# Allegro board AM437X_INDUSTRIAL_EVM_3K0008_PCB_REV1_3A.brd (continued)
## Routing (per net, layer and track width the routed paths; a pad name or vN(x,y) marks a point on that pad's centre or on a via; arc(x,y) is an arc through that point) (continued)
N18075606: length 13.7
  TOP w0.13: U11.T23 82.75,73.96 82.75,77.39 84.25,78.89 84.25,80.23 84.05,80.43 84.05,81.76 84.71,82.42 R74.1
N18139095: length 1.9
  BOTTOM w0.13: U32.7 R300.1
N18167698: length 5.7
  TOP w0.13: C99.2 37.34,25.91 37.59,25.65 38.23,25.65 38.86,26.29 38.86,27.66 39.49,28.29 U23.3
N18181630: length 13.2
  TOP w0.13: R73.1 83.19,85.72 83.19,82.99 82.33,82.13 82.33,81.54 81.46,80.67 81.46,75.79 80.83,75.16 80.83,74.61 U11.P24
N18182281: length 127.2
  TOP w0.13: U23.26 39.49,37.85 v1(38.99,38.35)
  L4_SIG2 w0.13: v1(105.54,87.43) 105.54,87.61 101.51,91.64 100.24,91.64 95.57,96.31 95.57,100.9 v1(96.9,102.23) ; v1(38.99,38.35) 41.09,38.35 41.4,38.66 41.81,38.66 44.82,41.67 44.82,44.58 44.38,45.03 44.38,51.84 46.04,53.5 46.04,54.17 44.77,55.44 44.77,58.66 48.21,62.1 50.73,62.1 54.1,65.48 58.02,65.48 60.42,67.88 60.42,68.76 61.54,69.88 61.54,72.01 62.54,73.01 63.02,73.01 65.52,75.5 65.52,75.5 65.97,75.96 65.97,78.91 67.02,79.95 67.02,82.34 69.33,84.64 69.58,84.64 69.92,84.98 69.92,87.01 76.35,93.45 78.05,93.45 79.07,94.46 v1(81.13,94.46)
  BOTTOM w0.13: v1(81.13,94.46) 82.06,95.39 85.69,95.39 91.9,101.6 96.27,101.6 v1(96.9,102.23) ; R363.2 v1(105.54,87.43)
N18365828: length 4.4
  TOP w0.13: Q2.G 126.28,115.75 Q1.D 125.34,116.95 R2.1
N18365970: length 12.9
  TOP w0.13: v2(125.6,112.52) 125.73,112.65 129.06,112.65 129.18,112.53 129.65,112.53 129.99,112.87 129.99,115.5 R3.1 128.52,115.43 Q2.D
  BOTTOM w0.13: v2(125.6,112.52) 126.31,113.23 U28.3
N18405849: length 39
  TOP w0.13: R68.2 v2(109.98,87.5) ; U11.AC16 86.69,69.39 86.69,69.39 86.65,69.43 v1(86.65,69.45)
  L3_SIG1 w0.13: v1(86.65,69.45) 87.1,69.45 89.15,71.5 94.08,71.5 95.12,72.54 98.7,72.54 101.42,75.26 102.57,75.26 103.48,76.17 v2(104.04,76.17)
  L4_SIG2 w0.13: v2(104.04,76.17) 104.52,76.66 104.52,81.91 106.88,84.27 110.7,84.27 111.21,84.78 111.21,86.27 v2(109.98,87.5)
N18405956: length 45.7
  TOP w0.13: R58.2 v2(109.98,89.79) ; v1(85.68,67.98) U11.AA15
  L3_SIG1 w0.13: v2(105.54,81.15) 105.92,80.77 105.92,80.21 104.85,79.14 104.85,73.99 101.39,70.52 99.26,70.52 97.66,68.92 89.55,68.92 89.03,68.4 87.16,68.4 87.16,68.4 86.11,68.4 v1(85.68,67.98)
  L4_SIG2 w0.13: v2(105.54,81.15) 106.79,82.41 110.68,82.41 111.83,83.55 111.83,86.55 111.5,86.88 111.5,88.65 110.36,89.79 v2(109.98,89.79)
N21620210: length 15.7
  TOP w0.13: v1(69.72,107.19) C3.1 ; U4.3 v1(72.64,97.54)
  L3_SIG1 w0.13: v1(72.64,97.54) 71.13,99.05 71.13,105.02 70.72,105.43 70.72,106.7 70.23,107.19 v1(69.72,107.19)
  BOTTOM w0.13: R295.2 v1(69.72,107.19)
N21620213: length 16.1
  TOP w0.13: v1(71.5,107.19) 72.26,107.95 C4.1 ; U4.5 v1(73.94,97.41)
  L3_SIG1 w0.13: v1(73.94,97.41) 72.39,98.96 72.39,104.43 72.01,104.81 72.01,106.68 v1(71.5,107.19)
  BOTTOM w0.13: R294.2 72.26,107.95 v1(71.5,107.19)
N21620216: length 15.5
  TOP w0.13: U4.7 v1(75.24,97.41) ; v1(74.8,107.19) C5.1
  L3_SIG1 w0.13: v1(75.24,97.41) 73.66,98.99 73.66,104.14 74.42,104.9 74.42,106.81 v1(74.8,107.19)
  BOTTOM w0.13: R293.2 v1(74.8,107.19)
N21620219: length 16.8
  TOP w0.13: U4.9 76.54,97.88 v1(75.44,96.77) ; v1(77.34,107.31) C6.1
  L3_SIG1 w0.13: v1(77.34,107.31) 76.2,106.17 76.2,97.54 v1(75.44,96.77)
  BOTTOM w0.13: R292.2 v1(77.34,107.31)
N21620222: length 15.3
  TOP w0.13: v1(79.88,107.19) C7.1 ; U4.11 v1(77.84,97.41)
  L3_SIG1 w0.13: v1(79.88,107.19) 78.74,106.05 78.74,98.31 v1(77.84,97.41)
  BOTTOM w0.13: R291.2 v1(79.88,107.19)
N21620225: length 10.5
  TOP w0.13: v1(82.42,107.19) C8.1 ; U4.18 77.84,106.16 v1(78.87,107.19)
  L4_SIG2 w0.13: v1(82.42,107.19) 81.66,107.95 79.63,107.95 v1(78.87,107.19)
  BOTTOM w0.13: R290.2 v1(82.42,107.19)
N21620228: length 14.6
  TOP w0.13: v1(78.54,108.05) 78.54,107.62 76.54,105.62 U4.20 ; v1(84.96,107.19) C9.1
  L4_SIG2 w0.13: v1(84.96,107.19) 83.89,108.26 78.74,108.26 v1(78.54,108.05)
  BOTTOM w0.13: R289.2 v1(84.96,107.19)
N21620231: length 21.6
  TOP w0.13: v1(76.3,108.31) 76.3,106.78 75.24,105.72 U4.22 ; v1(88.14,106.81) 88.14,108.65 C10.1
  L4_SIG2 w0.13: v1(76.3,108.31) 76.71,108.71 86.23,108.71 v1(88.14,106.81)
  BOTTOM w0.13: R288.2 87.5,107.44 v1(88.14,106.81)

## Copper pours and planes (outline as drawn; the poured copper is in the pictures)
AGND on TOP (solid shape): 127.95,110.04 127.95,106.23 127.25,105.54 125.15,105.54 125.1,105.57 125.11,105.62 125.16,105.67 125.16,107.25 125.92,108.01 125.92,108.23 125.92,109.79 126.3,110.17 127.82,110.17
AGNDFRAME_PRUETH0 on L5_PWR: 8.76,102.62 11.3,102.62 11.68,102.23 11.68,81.79 10.92,81.03 9.14,81.03 8.38,81.79 8.38,102.23
AGNDFRAME_PRUETH1 on L5_PWR: 8.51,58.04 8.51,78.11 8.89,78.49 11.43,78.49 11.68,78.23 11.68,58.04 11.18,57.53 9.02,57.53
DGND on TOP (solid shape): 30.48,50.42 30.48,48.89 30.23,48.64 28.07,48.64 27.81,48.89 27.81,50.42 28.07,50.67 30.23,50.67
DGND on TOP (solid shape): 46.99,58.67 46.99,55.63 46.74,55.37 45.21,55.37 44.96,55.63 44.96,58.67 45.21,58.93 46.74,58.93
DGND on TOP (solid shape): 52.07,71.88 52.07,70.1 51.56,69.6 49.66,69.6 49.15,70.1 49.15,72.14 49.52,72.5 51.45,72.5
DGND on TOP (solid shape): 52.2,78.74 52.2,76.2 51.94,75.95 49.78,75.95 49.28,76.45 49.28,78.74 49.78,79.25 51.69,79.25
DGND on TOP (solid shape): 63.25,115.82 63.25,111.63 62.99,111.38 61.47,111.38 61.21,111.63 61.21,115.82 61.47,116.08 62.99,116.08
DGND on TOP (solid shape): 110.62,38.23 110.62,35.18 110.36,34.92 108.84,34.92 108.58,35.18 108.58,38.23 108.84,38.48 110.36,38.48
DGND on TOP (solid shape): 112.9,75.56 112.9,72.52 112.65,72.26 111.31,72.26 111,72.58 111,75.63 111.19,75.82 112.65,75.82
DGND on TOP (solid shape): 52.07,65.91 52.07,63.88 51.43,63.25 49.69,63.25 49.15,63.79 49.15,65.15 49.41,65.42 50.05,65.42 50.68,66.04 51.94,66.04
DGND on TOP (solid shape): 127.76,41.78 127.76,40.13 127.38,39.75 123.6,39.75 121.92,39.75 121.54,40.13 121.54,42.04 122.17,42.67 126.87,42.67
DGND on TOP (solid shape): 48.39,34.54 48.39,31.56 48.2,31.19 48.39,30.82 48.39,28.19 48.26,28.07 46.66,28.07 46.46,28.27 46.46,29.87 41.28,29.87 41.28,30.1 40.26,30.1 40.26,29.87 37.46,29.87 37.46,28.58 36.58,28.58 36.58,34.04 36.83,34.29 37.34,34.29 37.59,34.04 37.59,33.53 47.37,33.53 47.37,34.67 48.26,34.67
DGND on BOTTOM (solid shape): 36.83,48.26 36.83,45.08 36.45,44.7 33.78,44.7 33.4,45.09 33.4,48.13 33.66,48.39 36.7,48.39
DGND on BOTTOM (solid shape): 44.96,45.59 44.96,42.04 44.58,41.66 42.42,41.66 42.16,41.91 42.16,45.59 42.42,45.85 44.7,45.85
DGND on BOTTOM (solid shape): 52.07,74.04 52.07,70.1 51.56,69.6 49.66,69.6 49.18,70.07 49.18,72.42 50.93,74.17 51.94,74.17
DGND on BOTTOM (solid shape): 52.07,67.82 52.07,64.01 51.31,63.25 49.66,63.25 49.18,63.72 49.18,66.32 50.8,67.95 51.94,67.95
DGND on BOTTOM (solid shape): 52.2,80.65 52.2,76.71 51.43,75.95 49.78,75.95 49.28,76.45 49.28,78.99 51.05,80.77 52.07,80.77
DGND on BOTTOM (solid shape): 107.7,106.43 107.7,104.96 107.44,104.71 105.73,104.71 105.41,105.03 105.41,106.43 105.79,106.81 107.31,106.81
DGND on BOTTOM (solid shape): 115.7,89.28 115.7,85.6 115.44,85.34 113.16,85.34 112.9,85.6 112.9,89.15 113.28,89.53 115.44,89.53
DGND on BOTTOM (solid shape): 17.4,59.94 17.4,57.66 14.83,57.66 14.57,57.4 14.35,57.4 13.97,57.78 13.97,59.82 14.48,60.32 17.02,60.32
DGND on BOTTOM (solid shape): 113.41,51.94 113.41,48.26 113.16,48.01 110.87,48.01 110.62,48.26 110.62,50.7 110.62,50.7 110.62,51.82 111,52.2 113.16,52.2
DGND on BOTTOM (solid shape): 124.46,86.11 124.46,82.93 124.08,82.55 122.11,82.55 122.1,82.55 121.97,82.58 121.84,82.55 121.83,82.55 121.41,82.55 121.03,82.93 121.03,86.11 121.41,86.49 124.08,86.49
DGND on BOTTOM (solid shape): 43.69,36.2 43.69,33.78 43.94,33.53 47.62,33.53 47.88,33.27 47.88,30.1 47.62,29.84 38.1,29.84 37.72,30.23 37.72,33.27 37.97,33.53 41.27,33.53 41.53,33.78 41.53,36.2 41.71,36.38 41.74,36.36 42.04,36.34 42.26,36.55 42.27,36.58 43.31,36.58
DGND on BOTTOM (solid shape): 121.16,48.39 121.44,47.86 122.13,47.79 122.17,47.71 122.17,45.59 121.79,45.21 119.54,45.21 119.29,45.44 118.95,45.43 118.92,45.42 118.75,45.59 118.75,48.77 119.13,49.15 121.16,49.15
DGND on BOTTOM (solid shape): 114.3,71.25 114.68,70.87 114.68,69.22 114.43,68.96 113.97,68.96 113.9,69 113.87,69.07 113.41,69.55 112.95,69.07 112.93,69 112.85,68.96 112.62,68.96 112.62,68.96 112.14,68.96 111.76,69.34 111.76,70.74 112.27,71.25
DGND on BOTTOM (solid shape): 52.07,58.42 52.07,54.48 51.68,54.09 51.58,54.07 51.51,54.15 51.02,54.56 50.6,54.08 50.57,54.01 50.5,53.98 50.32,53.98 50.24,54.01 50.22,54.08 49.92,54.53 49.4,54.39 49.33,54.35 49.25,54.38 49.18,54.45 49.18,56.8 50.93,58.55 51.94,58.55
DGND on BOTTOM (solid shape): outline of 97 points within 123.57,52.32 131.57,59.94
DGND on TOP: 127.38,77.09 124.21,77.09 123.83,77.47 123.83,79.12 124.84,80.14 124.84,81.03 125.48,81.66 127.38,81.66 127.76,81.28 127.76,77.47
DGND on TOP: 78.11,64.01 78.61,64.01 79.17,63.45 85.08,63.45 85.73,64.1 85.73,64.38 84.58,65.53 84.58,67.31 83.57,68.33 83.57,69.85 84.45,70.74 84.45,71.38 83.95,71.88 83.06,71.88 82.42,71.25 76.83,71.25 76.37,70.78 76.37,70.57 76.83,70.1 76.83,68.45 77.47,67.82 77.47,64.64
DGND on TOP: 33.27,62.48 35.31,62.48 35.81,61.98 35.81,60.32 34.92,59.44 34.54,59.44 33.15,60.83 31.62,60.83 30.48,61.98 30.48,64.26 30.73,64.52 31.24,64.52
DGND on TOP: 41.66,63.37 46.23,63.37 49.28,60.32 58.29,60.32 59.31,61.34 67.31,61.34 67.56,61.09 67.56,60.45 66.8,59.69 59.56,59.69 58.67,58.8 49.15,58.8 47.21,60.74 42.02,60.74 41.15,61.62 41.15,62.86
DGND on TOP: 64.01,116.08 65.41,116.08 66.42,115.06 66.42,112.9 66.17,112.65 64.9,112.65 63.75,113.79 63.75,115.82
DGND on TOP: 61.85,31.5 62.48,31.5 62.86,31.88 63.12,31.88 63.37,31.62 64.52,31.62 64.9,31.24 64.9,29.59 64.39,29.08 62.86,29.08 61.59,30.35 61.59,31.24
DGND on TOP: 33.4,73.28 33.78,72.9 33.78,71.63 33.27,71.12 28.96,71.12 28.7,71.37 28.7,72.64 29.34,73.28
DGND on TOP: 81.58,91.03 79.04,91.03 78.28,91.8 78.28,93.78 78.59,94.08 81.33,94.08 81.84,93.57 81.84,91.29
DGND on TOP: 38.1,84.96 39.62,84.96 40,84.58 40,80.14 46.1,74.04 46.1,72.14 48.89,69.34 57.78,69.34 58.17,68.96 58.17,68.33 57.02,67.18 48.51,67.18 44.32,71.37 44.32,73.91 40.26,77.98 39.5,77.98 37.59,79.88 37.59,84.45
DGND on TOP: 31.37,52.83 30.99,52.45 30.35,52.45 30.1,52.7 30.1,53.72 29.34,54.48 27.18,54.48 27.05,54.61 27.05,55.88 27.18,56.01 30.48,56.01 31.37,55.12
DGND on TOP: 47.37,111.63 47.88,112.14 48.77,112.14 49.15,111.76 49.15,110.87 50.29,109.73 50.29,107.82 49.15,106.68 49.15,106.05 48.77,105.66 47.88,105.66 47.37,106.17
DGND on TOP: 33.66,44.32 36.83,44.32 36.96,44.45 36.96,45.72 36.83,45.85 33.66,45.85 33.4,45.59 33.4,44.58
DGND on TOP: 87.76,96.65 93.6,96.65 94.23,96.01 94.23,93.73 93.85,93.34 87.63,93.34 87.12,93.85 87.12,96.01
DGND on TOP: 87.38,84.71 89.53,84.71 90.04,85.22 90.04,86.23 88.77,87.5 87.63,87.5 87.12,87 87.12,84.96
DGND on TOP: 18.29,100.71 22.48,100.71 23.11,100.08 34.67,100.08 35.18,99.57 35.18,97.66 34.67,97.16 22.48,97.16 20.7,98.93 19.81,98.93 18.92,98.04 17.78,98.04 17.14,98.68 17.14,99.57
DGND on TOP: 23.62,22.99 26.67,22.99 28.07,21.59 28.07,16 27.56,15.49 23.49,15.49 23.11,15.88 23.11,22.48
DGND on TOP: 92.58,16.89 92.08,16.89 91.31,17.65 89.53,17.65 88.9,18.29 88.9,19.43 89.15,19.69 91.57,19.69 91.82,19.43 91.82,18.16 92.58,17.4
DGND on TOP: 33.4,49.4 31.62,49.4 31.37,49.66 31.37,52.2 32.13,52.96 32.13,53.59 32.51,53.98 33.78,53.98 33.91,53.85 33.91,49.91
DGND on TOP: 37.34,76.58 41.02,76.58 41.4,76.2 41.4,74.8 41.02,74.42 37.34,74.42 36.96,74.8 36.96,76.2
DGND on TOP: 117.22,27.05 118.87,27.05 120.52,28.7 120.52,32.77 120.02,33.27 113.03,33.27 111.63,31.88 111.63,27.43 112.52,26.54 116.71,26.54
DGND on BOTTOM: 103,94.87 102.71,94.58 102.46,94.58 102.14,94.9 103,95.76 103.63,95.76 105.16,97.28 105.16,98.3 105.41,98.55 106.43,98.55 106.68,98.3 106.68,95.12 106.43,94.87
DGND on BOTTOM: 81.84,91.29 81.58,91.03 79.02,91.03 78.23,91.82 78.23,93.73 78.59,94.08 81.33,94.08 81.84,93.57
DGND on BOTTOM: 33.4,99.69 35.18,99.69 40.13,94.74 40.13,94.49 35.69,94.49 35.31,94.87 35.31,96.01 33.91,97.41 33.02,97.41 32.38,98.04 32.38,98.68
DGND on BOTTOM: 26.54,92.84 30.56,92.84 30.99,92.41 30.99,91.19 30.73,90.93 29.72,90.93 28.58,89.79 26.54,89.79 26.16,90.17 26.16,92.46
DGND on BOTTOM: 45.09,18.41 45.09,16.89 44.7,16.51 41.27,16.51 41.02,16.76 41.02,18.54 41.27,18.8 44.7,18.8
DGND on BOTTOM: 119.89,29.84 120.52,30.48 120.52,33.15 119.13,34.54 113.03,34.54 111.63,33.15 111.63,30.73 112.52,29.84
DGND on BOTTOM: 40.51,89.66 41.15,89.66 41.4,89.41 41.4,87 40.13,85.72 40.13,84.07 39.37,83.31 37.08,83.31 36.83,83.57 36.83,85.98
DGND on BOTTOM: 12.83,22.86 15.11,22.86 15.49,22.48 15.49,21.21 14.61,20.32 14.61,16.89 14.1,16.38 12.95,16.38 12.45,16.89 12.45,22.48
DGND on BOTTOM: 87.76,87.5 89.28,87.5 90.04,86.74 90.04,85.72 89.28,84.96 87.76,84.96 87.38,85.34 87.38,87.12
DGND on BOTTOM: 76.45,69.72 76.45,70.87 77.47,71.88 81.15,71.88 81.79,71.25 83.44,71.25 83.82,71.63 85.34,71.63 85.85,71.12 87.25,71.12 87.38,71.25 87.38,71.63 87.63,71.88 90.04,71.88 90.3,71.63 90.3,69.85 89.28,68.83 87.63,68.83 87.12,68.33 87.12,63.88 86.74,63.5 82.93,63.5 82.68,63.75 81.53,63.75 81.28,63.5 79.38,63.5 79.25,63.37 77.6,63.37 77.47,63.5 76.58,63.5 76.07,64.01 76.07,69.34 ; 1 cut-out
DGND on BOTTOM: 65.15,115.06 65.41,115.32 66.8,115.32 66.93,115.44 66.93,116.59 66.8,116.71 61.59,116.71 61.09,116.2 61.09,111.89 61.47,111.51 63.12,111.51 63.5,111.89 64.9,111.89 65.15,112.14
DGND on BOTTOM: 71.5,99.57 74.42,99.57 75.95,98.04 77.22,98.04 77.47,98.3 77.47,99.44 77.85,99.82 81.66,99.82 82.04,100.2 82.04,101.47 81.79,101.73 80.26,101.73 80.01,101.98 80.01,105.66 79.5,106.17 77.22,106.17 76.71,105.66 76.71,103.89 76.2,103.38 74.17,103.38 73.02,102.23 71.5,102.23 71.12,101.85 71.12,99.95
DGND on BOTTOM: 129.16,114.68 130.56,114.68 130.81,114.94 131.19,114.94 131.44,114.68 131.44,113.03 131.19,112.78 129.16,112.78 128.91,113.03 128.91,114.43
DGND on BOTTOM: 56.52,70.61 57.78,70.61 58.67,69.72 62.23,69.72 63.12,70.61 66.04,70.61 68.83,67.82 72.52,67.82 72.64,67.69 72.64,67.31 72.39,67.06 56.52,67.06 55.75,67.82 55.75,69.85
DGND on BOTTOM: 99.82,98.68 99.31,99.19 97.28,99.19 96.77,98.68 96.77,96.65 97.28,96.14 99.44,96.14 99.82,96.52
DGND on BOTTOM: 7.37,11.05 9.91,11.05 10.29,10.67 10.29,8.51 9.53,7.75 7.75,7.75 6.99,8.51 6.99,10.67
DGND on BOTTOM: 33.73,57.68 31.62,59.79 31.62,61.47 32.26,62.1 35.94,62.1 35.94,60.96 38.23,60.96 39.12,60.07 39.12,59.31 37.49,57.68
DGND on BOTTOM: 65.91,105.16 66.93,105.16 67.18,104.9 67.18,103.12 65.53,101.47 63.12,101.47 62.61,101.98 62.61,104.01 63.12,104.52 63.88,104.52 64.14,104.77 64.14,106.68 64.39,106.93 65.15,106.93 65.66,106.43 65.66,105.41
DGND on BOTTOM: 101.22,88.27 100.84,87.88 98.81,87.88 98.42,88.27 98.42,90.8 100.71,93.09 101.24,93.09 101.37,92.96 101.37,92.1 101.22,91.95
DGND on BOTTOM: 114.17,16 119.89,16 120.52,15.37 120.52,11.05 119.51,10.03 114.3,10.03 113.28,11.05 113.28,15.11
DGND on BOTTOM: 23.49,22.86 26.8,22.86 27.43,22.23 27.43,19.94 28.07,19.3 28.07,16.38 26.8,15.11 23.75,15.11 23.11,15.75 23.11,22.48
DGND on BOTTOM: 56.64,96.01 67.95,96.01 68.2,96.27 68.2,97.92 67.82,98.3 56.77,98.3 56.39,97.92 56.39,96.27
DGND on BOTTOM: 98.3,45.21 102.49,45.21 103.12,44.58 103.12,42.16 102.49,41.53 98.42,41.53 97.79,42.16 97.79,44.7
DGND on L2_GND: 2.53,118.73 137.17,118.73 138.71,117.2 138.71,2.18 137.8,1.27 54.51,1.27 53.91,1.87 42.23,1.87 41.63,1.27 2.54,1.27 1.3,2.51 1.3,117.5
DGND on L3_SIG1: 16.76,102.87 20.07,102.87 22.48,100.46 22.48,93.34 20.07,90.93 20.07,87.63 20.7,87 29.34,87 30.61,85.72 30.61,84.58 29.59,83.57 20.07,83.57 19.3,82.8 19.3,76.71 25.91,70.1 25.91,65.79 27.81,63.88 29.21,63.88 29.97,63.12 29.97,61.98 29.34,61.34 26.8,61.34 21.34,66.8 21.34,69.98 14.99,76.33 14.99,83.82 14.22,84.58 14.22,100.33
DGND on L3_SIG1: 29.59,72.14 38.96,72.14 41.91,69.19 53.37,69.19 58.12,64.43 60.92,64.43 61.85,63.5 63.63,63.5 63.88,63.25 63.88,62.23 63.12,61.47 58.04,61.47 53.75,65.76 48.51,65.76 48.23,66.04 41.99,66.04 37.8,70.23 29.84,70.23 29.08,70.99 29.08,71.63 ; 1 cut-out
DGND on L3_SIG1: 47.24,90.55 50.19,90.55 53.11,87.63 58.67,87.63 61.34,84.96 61.34,78.23 61.77,77.8 61.77,73.33 56.98,68.54 55.88,69.65 55.88,71.25 59.56,74.93 59.56,76.45 59.84,76.73 59.84,78.84 59.82,78.87 59.82,84.84 58.93,85.72 54.74,85.72 54.23,85.22 50.55,85.22 46.86,88.9 46.86,90.17
DGND on L4_SIG2: 63.3,75.36 63.3,76.23 61.39,78.13 61.39,85.65 61.93,86.18 61.93,87.27 61.61,87.59 60.68,87.59 59.82,86.73 59.82,77.8 59.79,77.77 59.79,75.62 59.41,75.23 57.07,75.23 55.44,73.6 55.44,70.24 56.13,69.55 57.2,69.55 57.53,69.88 57.53,70.1 57.78,70.36 57.84,70.36 59.99,72.52 60.45,72.52
DGND on L4_SIG2: 16.51,103 22.23,103 22.86,102.36 22.86,71.75 25.02,69.6 25.02,67.44 24.51,66.93 22.35,66.93 19.3,69.98 19.3,72.26 14.86,76.71 14.86,101.35
DGND on L4_SIG2: 50.18,85.61 47.19,88.6 47.19,89.94 47.57,90.32 56.62,90.32 57.4,89.53 57.4,86.23 56.78,85.61
DGND on L5_PWR: 94.23,55.12 94.23,54.46 94.84,53.85 95.5,53.85 96.81,52.54 96.81,49.62 102.36,44.07 102.69,44.07 103.12,43.64 103.12,21.84 100.2,18.92 95.15,18.92 93.88,20.19 73.66,20.19 64.77,29.08 64.77,30.35 62.36,32.77 62.36,51.43 64.77,53.85 64.77,54.99 66.29,56.52 66.29,57.53 67.44,58.67 67.82,58.67 70.74,61.59 74.68,61.59 75.31,62.23 77.85,62.23 79.12,63.5 83.44,63.5 84.45,64.52 85.47,64.52 85.72,64.26 85.72,63.63
GND_ETH1 on BOTTOM: 26.67,108.33 45.85,108.33 47.5,109.98 47.5,112.39 47.24,112.65 27.43,112.65 26.16,113.92 25.53,113.92 25.27,113.66 25.27,109.73
GND_OSC0 on TOP: 69.72,79.25 69.72,89.79 71.12,91.19 74.8,91.19 75.56,90.42 75.56,85.98 74.55,84.96 74.55,75.44 73.91,74.8 72.9,74.8 72.64,75.06 72.64,76.33
GND_OSC0 on L2_GND: 70.61,81.28 70.61,90.17 71.63,91.19 74.8,91.19 75.56,90.42 75.56,85.98 74.9,85.32 74.9,75.79 73.91,74.8 73.3,74.8 73.15,74.96 73.15,78.74
GND_OSC1 on BOTTOM: 102.74,64.26 103.25,63.75 103.25,58.29 102.74,57.78 91.95,57.78 89.92,59.82 88.77,59.82 87.5,61.09 86.87,61.09 86.61,61.34 86.61,62.36 88.52,64.26 ; 1 cut-out
GNDA_ADC on TOP: 120.02,117.86 121.92,115.95 121.92,109.35 121.16,108.58 118.62,108.58 117.73,107.7 115.57,107.7 115.19,107.31 113.92,107.31 112.9,108.33 112.9,115.7 115.06,117.86
GNDA_ADC on TOP: 63.88,31.88 64.77,31.88 65.79,30.86 65.79,28.32 66.8,27.3 66.8,22.1 74.93,13.97 77.34,13.97 78.41,15.04 78.41,17.86 67.18,29.08 67.18,31.88 66.17,32.89 64.01,32.89 63.63,32.51 63.63,32.13
GNDA_ADC on TOP: 112.14,90.3 115.7,90.3 116.33,90.93 116.97,90.93 117.22,90.68 117.22,87.5 116.71,87 112.14,87 111.89,87.25 111.89,90.04
GNDA_ADC on L3_SIG1: 105.84,76.07 107.57,76.07 108.01,75.63 108.01,74.99 108.33,74.68 108.33,73.28 111.89,69.72 111.89,66.93 110.24,65.28 108.84,65.28 105.41,61.85 88.27,61.85 87.38,62.74 87.38,63.25 87.76,63.63 103.25,63.63 104.27,64.64 104.27,66.04 103,67.31 100.84,67.31 100.84,69.77 105.21,74.14 105.21,75.44
GNDA_ADC on L4_SIG2: 93.85,42.42 96.27,42.42 97.16,41.53 97.16,37.08 96.52,36.45 95.5,36.45 93.22,38.73 93.22,41.78
GNDUSBJ on BOTTOM (solid shape): 136.87,60.8 136.87,59.29 137.58,59.29 137.58,59.56 138.66,59.56 138.66,55.12 135.73,55.12 135.23,55.63 135.23,60.93 136.75,60.93
GNDUSBJ on BOTTOM (solid shape): 138.66,70.1 138.66,66.09 137.58,66.09 137.58,66.69 136.87,66.69 136.87,65.06 136.84,65.02 136.69,65.02 136.65,65.06 135.15,65.06 135.1,65.11 135.1,65.6 134.81,65.89 134.81,70.23 135.06,70.48 138.27,70.48
GNDUSBJ on L3_SIG1: 136.4,56.13 135.64,56.9 135.64,58.55 136.53,59.44 136.53,69.85 137.03,70.36 138.3,70.36 138.73,69.93 138.73,56.94 137.92,56.13
V1_5D on TOP: 129.29,100.46 131.06,100.46 131.44,100.08 131.44,98.3 131.06,97.92 129.41,97.92 128.91,98.42 128.91,100.08
V1_5D on TOP: 128.14,89.03 129.79,89.03 130.18,88.65 130.18,88.01 129.79,87.63 128.14,87.63 127.89,87.88 127.89,88.77
V1_5D on BOTTOM: 60.45,40.89 61.34,40 62.74,40 62.99,40.26 62.99,41.15 62.23,41.91 62.23,43.94 58.04,48.13 49.78,48.13 49.15,48.77 45.72,48.77 45.21,48.26 45.21,44.07 48.39,40.89
V1_5D on BOTTOM: 80.39,63.25 81.03,63.25 81.53,62.74 81.53,62.36 80.77,61.59 80.77,58.8 80.52,58.55 80.14,58.55 79.88,58.8 79.88,62.74
V1_5D on L3_SIG1: 128.4,88.9 129.41,88.9 129.79,88.52 129.79,86.23 129.54,85.98 129.16,85.98 127.89,87.25 127.89,88.39
V1_5D on L3_SIG1: 51.56,43.05 54.48,43.05 61.09,36.45 62.36,36.45 62.61,36.7 62.61,44.45 66.42,48.26 67.82,48.26 78.87,59.31 79.63,59.31 81.28,60.96 81.28,62.1 82.04,62.86 83.44,62.86 83.69,63.12 83.69,63.88 83.31,64.26 77.47,64.26 61.21,48.01 51.56,48.01 50.67,47.12 50.67,43.94
V1_5D on L3_SIG1: 96.27,24.13 100.08,24.13 100.84,23.37 100.84,22.1 96.58,17.84 94.17,17.84 92.96,16.64 91.57,16.64 90.8,17.4 90.8,18.67
V1_5D on L4_SIG2: 78.99,64.26 83.19,64.26 83.69,63.75 83.69,62.86 83.06,62.23 78.99,62.23 78.49,62.74 78.49,63.75
V1_5DREG on BOTTOM (solid shape): 45.85,52.07 45.85,51.69 43.31,49.15 42.8,49.15 41.53,47.88 41.53,46.86 39.62,44.96 37.46,44.96 37.21,45.21 37.21,51.31 37.46,51.56 43.56,51.56 44.32,52.32 45.59,52.32
V1_8D on TOP: 94.36,100.97 99.31,100.97 99.69,100.58 99.69,99.19 99.31,98.81 98.17,98.81 97.66,99.31 94.23,99.31 94.11,99.44 94.11,100.71
V1_8D on BOTTOM: 112.27,87.38 109.98,87.38 108.08,85.47 108.08,82.93 108.71,82.3 112.14,82.3 112.65,82.8 112.65,87
V1_8D on L3_SIG1: 104.77,60.32 106.81,60.32 107.44,59.69 107.44,53.72 108.97,52.2 108.97,50.67 108.46,50.16 104.39,50.16 103.63,50.93 103.63,59.18
V1_8D on L4_SIG2: 106.05,86.87 106.05,87.73 98.81,94.97 98.81,104.52 105.92,111.63 106.81,111.63 107.34,111.1 107.34,103.48 106.02,102.16 106.02,92.99 108.58,90.42 108.58,88.27 110.74,86.11 110.74,84.96 110.49,84.71 108.2,84.71
V1_8D on L5_PWR: 108.71,86.11 111,86.11 111.76,85.34 111.76,60.83 108.08,57.15 105.66,57.15 105.47,57.34 105.47,60.01 108.08,62.61 108.08,63.75 104.39,67.44 104.39,76.58 107.95,80.14 107.95,85.34
V1_8D_AM437X on TOP: 81.84,88.62 81.46,88.24 78.64,88.24 78.23,88.65 78.23,90.42 78.59,90.78 81.58,90.78 81.84,90.53
V1_8D_AM437X on TOP: 94.36,98.93 96.14,98.93 96.9,98.17 96.9,97.16 96.39,96.65 95.76,96.65 95.12,97.28 94.36,97.28 94.11,97.54 94.11,98.68
V1_8D_AM437X on BOTTOM: 81.43,90.78 81.84,90.37 81.84,88.62 81.46,88.24 79.3,88.24 78.61,88.93 78.61,90.3 79.1,90.78
V1_8D_AM437X on BOTTOM: 86.74,91.06 89.41,91.06 89.66,91.31 89.66,93.34 89.28,93.73 86.74,93.73 86.23,93.22 86.23,91.57
V1_8D_AM437X on BOTTOM: 103.76,72.14 105.16,72.14 105.28,72.01 105.28,69.22 105.03,68.96 104.01,68.96 102.84,67.79 102.26,67.79 101.88,68.17 101.88,69.11 102.49,69.72 103,69.72 103.63,70.36 103.63,72.01
V1_8D_AM437X on BOTTOM: 69.34,83.57 71.12,83.57 71.63,83.06 71.63,81.66 71.5,81.53 69.85,81.53 69.09,82.3 69.09,83.31
V1_8D_AM437X on L3_SIG1: 73.79,72.77 73.02,72.77 72.2,73.6 72.2,78.42 76.66,82.88 76.66,88.09 83.57,95 91.06,95 95.15,99.09 99.16,99.09 100.33,97.92 100.33,95.81 96.08,91.55 90.82,91.55 89.87,90.6 84.63,90.6 80.77,86.74 80.77,81.65 75.95,76.82 75.95,74.93
V1_8D_AM437X on L5_PWR: 103.63,59.44 96.06,67.01 96.06,79.81 98.42,82.17 98.42,89.79 96.39,91.82 85.98,91.82 82.8,88.65 78.23,88.65 77.47,89.41 75.69,89.41 70.61,84.33 70.61,82.3 69.85,81.53 68.83,81.53 68.07,82.3 68.07,85.09 67.56,85.6 67.56,87.5 68.52,88.46 70.42,88.46 72.33,90.36 73.85,90.36 74.68,91.19 83.06,91.19 86.11,94.23 90.04,94.23 94.36,98.55 96.77,98.55 101.47,93.85 101.47,79.76 100.46,78.74 100.46,74.17 103.76,70.87 103.76,68.2 108.08,63.88 108.08,62.36 105.16,59.44
V1_8DADC on BOTTOM: 127.89,115.19 131.85,115.19 132.21,115.54 132.21,116.59 131.95,116.84 128.27,116.84 127.76,116.33 127.76,115.32
V1_8DREG on BOTTOM (solid shape): outline of 136 points within 112.01,78.87 120.65,87.12
V1_8FTDI on BOTTOM: 111.76,57.78 112.14,57.4 112.14,56.13 111.76,55.75 109.73,55.75 109.35,56.13 109.35,57.4 109.73,57.78
V1_8FTDI on L3_SIG1: 111.38,55.5 111.76,55.12 119.89,55.12 120.4,55.63 120.4,60.32 123.57,63.5 126.62,63.5 127.64,62.48 127.64,55.75 124.08,52.2 109.55,52.2 107.89,53.85 107.89,62.86 108.81,63.78 110.49,63.78 110.49,63.75 111.38,62.86
V2_5MTR on L5_PWR: 51.43,39.37 55.37,39.37 59.56,35.18 59.56,28.58 57.4,26.42 51.18,26.42 49.91,27.69 49.91,37.85
V2_8A on TOP (solid shape): 130.62,112.2 130.62,110.8 130.36,110.55 126.04,110.55 125.54,110.04 125.54,108.39 124.77,107.63 124.77,107.12 124.77,106.61 124.77,105.83 124.62,105.67 124.51,105.65 124.44,105.74 124.44,105.91 124.08,106.27 124.08,106.67 123.76,106.99 123.76,107.5 123.85,107.68 123.89,107.88 123.89,108.65 123.85,108.85 123.76,109.03 123.76,109.79 126.17,112.2 128.87,112.2 128.99,112.09 129.84,112.09 130.28,112.53
V2_8D on TOP: 128.78,110.24 131.19,110.24 131.44,109.98 131.44,109.09 130.94,108.58 128.91,108.58 128.65,108.84 128.65,110.11
V2_8D on TOP: 116.84,92.84 116.84,91.57 116.59,91.31 115.82,91.31 115.57,91.57 115.57,93.85 116.46,94.74 117.86,94.74 118.11,94.49 118.11,93.34 117.86,93.09 117.09,93.09
V2_8D on BOTTOM: 116.2,104.9 117.98,104.9 118.24,105.16 118.24,107.95 117.73,108.46 116.46,108.46 115.95,107.95 115.95,105.16
V2_8D on L4_SIG2: 135.38,96.52 132.59,93.73 117.86,93.73 116.2,95.38 116.2,107.44 121.03,112.27 130.05,112.27 132.33,109.98 132.33,100.84 135.38,97.79
V2_8D_OUT on BOTTOM (solid shape): 117.6,104.27 117.6,102.49 117.35,102.23 110.74,102.23 110.55,102.43 110.56,102.43 110.56,103.95 110.62,104.01 110.87,104.01 110.88,104.01 111.01,103.96 111.15,103.95 114.05,103.95 114.05,104 114.07,104.01 114.17,104.01 114.55,104.39 117.47,104.39
V3_3D on TOP (solid shape): 52.07,56.39 52.07,54.36 51.43,53.72 49.66,53.72 49.15,54.23 49.15,55.4 49.3,55.4 49.3,55.34 49.31,55.28 49.32,55.22 49.35,55.17 49.38,55.12 49.41,55.07 49.46,55.03 49.5,54.99 49.56,54.96 49.61,54.94 49.67,54.92 49.73,54.91 49.79,54.91 49.85,54.92 49.91,54.94 49.96,54.96 50.01,54.99 50.06,55.03 50.1,55.07 50.14,55.12 50.17,55.17 50.19,55.22 50.21,55.28 50.22,55.34 50.22,55.4 50.21,55.46 50.19,55.52 50.17,55.57 50.14,55.63 50.1,55.67 50.06,55.72 50.01,55.75 49.96,55.78 49.91,55.81 49.85,55.82 49.79,55.83 49.73,55.83 49.67,55.82 49.61,55.81 49.56,55.78 49.5,55.75 49.46,55.72 49.41,55.67 49.38,55.63 49.35,55.57 49.32,55.52 49.31,55.46 49.3,55.4 49.15,55.4 49.15,56.26 49.29,56.39 49.31,56.39 49.34,56.39 49.37,56.38 49.42,56.33 49.46,56.29 49.51,56.25 49.57,56.23 49.62,56.2 49.68,56.19 49.74,56.18 49.8,56.19 49.86,56.2 49.92,56.21 49.97,56.24 50.03,56.27 50.07,56.31 50.11,56.35 50.15,56.4 50.18,56.45 50.2,56.52 51.94,56.52
V3_3D on BOTTOM (solid shape): 123.7,66.8 123.7,66.17 121.41,63.88 118.75,63.88 118.49,64.14 118.49,65.15 118.62,65.28 119.86,65.28 119.98,65.41 120.02,65.41 120.33,65.72 120.33,67.24 120.91,67.82 122.68,67.82
V3_3D on BOTTOM (solid shape): 107.82,104.07 108.97,104.07 109.09,103.95 109.09,102.92 109.05,102.83 108.36,102.76 108.08,102.23 108.08,101.86 108.07,101.85 107.57,101.85 107.19,102.23 105.79,102.23 105.41,102.62 105.41,104.01 105.72,104.33 107.57,104.33
V3_3D on TOP: 94.49,10.79 94.49,11.3 94.77,11.58 94.77,13.13 95.71,13.13 96.27,12.57 98.55,12.57 98.81,12.83 98.81,14.48 99.57,15.24 100.2,15.24 100.33,15.11 100.33,10.92 100.08,10.67 94.61,10.67
V3_3D on TOP: 41.91,74.8 41.91,72.01 42.16,71.75 43.69,71.75 43.94,72.01 43.94,73.79 42.67,75.06 42.16,75.06
V3_3D on TOP: 94.87,106.43 92.2,106.43 91.57,105.79 91.57,102.87 91.69,102.74 92.84,102.74 93.09,103 93.09,103.89 93.22,104.01 95.25,104.01 95.38,104.14 95.38,105.92
V3_3D on TOP: 67.18,106.43 67.95,106.43 68.2,106.68 70.1,106.68 70.48,106.3 70.48,102.36 69.98,101.85 67.82,101.85 66.93,102.74 66.93,106.17
V3_3D on BOTTOM: 134.85,90.55 135.76,90.55 136.02,90.3 136.02,88.01 135.64,87.63 135.51,87.63 134.75,88.39 134.75,90.45
V3_3D on BOTTOM: 26.16,99.31 28.7,99.31 28.96,99.06 28.96,97.79 28.58,97.41 26.8,97.41 26.03,98.17 26.03,99.19
V3_3D on BOTTOM: 128.91,73.28 129.16,73.28 129.92,72.52 130.56,72.52 130.94,72.14 130.94,71.37 130.56,70.99 129.41,70.99 128.78,71.63 128.78,73.15
V3_3D on BOTTOM: 67.82,106.93 72.52,106.93 73.53,105.92 73.53,103.76 73.02,103.25 71.63,103.25 69.85,101.47 67.56,101.47 67.18,101.85 67.18,102.62 67.56,103 67.56,106.68
V3_3D on BOTTOM: 132.34,50.67 133.22,50.67 133.35,50.8 133.35,52.83 133.1,53.09 132.72,53.09 132.34,52.71
V3_3D on BOTTOM: 129.79,84.45 130.68,84.45 130.68,86.61 130.43,86.87 130.05,86.87 129.79,86.61
V3_3D on BOTTOM: 103,90.93 102.49,91.44 102.49,92.08 102.62,92.2 103.25,92.2 103.5,91.95 106.17,91.95 106.68,92.46 106.68,93.34 106.43,93.6 104.14,93.6 103.89,93.85 102.74,93.85 102.62,93.98 102.62,94.11 103.12,94.61 106.68,94.61 107.06,95 107.06,98.55 106.68,98.93 103.12,98.93 102.74,98.55 102.74,97.92 102.62,97.79 102.11,97.79 101.85,97.54 101.85,96.77 101.32,96.24 101.32,94.2 101.22,94.2 101.22,93.85 101.09,93.85 100.2,94.74 100.2,98.81 99.82,99.19 99.82,101.35 100.2,101.73 107.06,101.73 108.71,100.08 108.71,91.95 107.7,90.93
V3_3D on L3_SIG1: 119.13,46.86 128.27,46.86 129.54,45.59 129.54,43.05 128.4,41.91 119.13,41.91 118.11,42.93 118.11,45.85
V3_3D on L4_SIG2: 41.76,5.59 49.78,5.59 51.82,3.56 57.02,3.56 60.58,7.11 60.58,18.8 59.69,19.69 42.04,19.69 40.31,17.96 40.31,7.04
V3_3D on L4_SIG2: 136.4,76.45 127.25,85.6 119.38,85.6 117.6,87.38 117.6,91.44 119.13,92.96 134.62,92.96 135.89,94.23 135.89,98.3 132.97,101.22 132.97,108.2 133.6,108.84 135.38,108.84 136.53,107.7 136.53,102.62 138.68,100.46 138.68,77.22 137.92,76.45
V3_3D on L5_PWR: 3.16,118.1 46.12,118.1 47.37,116.84 47.37,107.7 49.02,106.05 82.55,106.05 84.43,107.92 89.41,107.92 91.29,106.05 117.47,106.05 120.02,103.5 120.02,73.02 125.09,67.95 125.09,65.41 120.02,60.32 120.02,41.66 111.76,33.4 111.76,15.88 109.22,13.34 100.71,13.34 99.95,12.57 99.06,12.57 98.3,13.34 33.81,13.34 28.45,18.69 28.45,28.19 31.5,31.24 31.5,36.58 37.46,42.55 37.46,58.67 36.07,60.07 33.66,60.07 26.03,52.45 26.03,49.91 24.38,48.26 3.17,48.26 1.91,49.53 1.91,116.84
V3_3D_AM437X on TOP (solid shape): 54.99,56.26 54.99,54.1 54.36,53.47 52.96,53.47 52.45,53.98 52.45,56.26 52.7,56.52 54.74,56.52
V3_3D_AM437X on TOP (solid shape): 55.24,65.48 55.24,63.88 54.61,63.25 52.83,63.25 52.45,63.63 52.45,64.26 52.45,64.77 52.45,66.04 52.46,66.05 54.67,66.05
V3_3D_AM437X on TOP (solid shape): 54.99,71.75 54.99,69.72 54.61,69.34 52.83,69.34 52.45,69.72 52.45,70.23 52.45,70.74 52.45,71.25 52.45,71.76 52.7,72.01 54.74,72.01
V3_3D_AM437X on TOP (solid shape): 55.12,77.82 55.12,76.5 55.1,76.47 55.07,76.45 54.81,76.33 54.71,76.05 54.69,75.98 54.61,75.95 52.96,75.95 52.58,76.33 52.58,76.71 52.58,77.22 52.58,77.72 52.58,78.61 52.83,78.87 54.07,78.87
V3_3D_AM437X on BOTTOM (solid shape): 54.99,56.9 54.99,54.1 54.36,53.47 52.96,53.47 52.45,53.98 52.45,58.29 52.7,58.55 53.34,58.55
V3_3D_AM437X on BOTTOM (solid shape): 55.24,66.29 55.24,63.88 54.61,63.25 52.83,63.25 52.45,63.63 52.45,66.17 52.45,66.68 52.45,67.69 52.7,67.95 53.59,67.95
V3_3D_AM437X on BOTTOM (solid shape): 54.99,72.52 54.99,69.98 54.36,69.34 52.96,69.34 52.45,69.85 52.45,70.23 52.45,70.74 52.45,71.25 52.45,71.76 52.45,73.91 52.7,74.17 53.34,74.17
V3_3D_AM437X on BOTTOM (solid shape): 55.12,79.12 55.12,76.58 55.06,76.52 55.04,76.52 54.78,76.39 54.65,76.13 54.65,76.11 54.48,75.95 53.34,75.95 52.58,76.71 52.58,78.99 52.58,79.5 52.58,80.01 52.58,80.52 52.83,80.77 53.47,80.77
V3_3D_AM437X on L3_SIG1: 83.57,68.83 82.68,69.72 77.85,69.72 77.34,69.22 77.34,65.15 77.72,64.77 77.72,62.99 77.47,62.74 76.83,62.74 75.95,63.63 75.95,70.48 77.72,72.26 79.76,72.26 81.91,74.42 86.61,74.42 86.61,69.98 85.47,68.83
V3_3D_AM437X on L5_PWR: 52.45,54.23 52.45,76.96 53.85,78.36 61.09,78.36 61.47,77.98 61.47,76.71 62.36,75.82 73.66,75.82 75.82,73.66 75.82,69.72 77.22,68.33 77.22,65.41 77.85,64.77 77.85,62.86 77.47,62.48 72.01,62.48 68.3,66.19 61.09,66.19 57.91,63.02 57.91,54.48 56.26,52.83 53.85,52.83
V3_3D_PRUETH0JCK on BOTTOM: 12.7,95.89 18.67,95.89 20.83,93.73 20.83,84.84 19.94,83.95 13.21,83.95 12.07,85.09 12.07,95.25
V3_3D_PRUETH1JCK on BOTTOM: 12.7,70.48 18.67,70.48 19.94,71.75 20.57,71.75 20.83,71.5 20.83,62.74 18.8,60.71 13.72,60.71 12.07,62.36 12.07,69.85
V3_3DREG on BOTTOM (solid shape): outline of 137 points within 53.26,102.74 67.06,111.51
V3_3DREG on L3_SIG1: 14.61,51.94 17.4,51.94 18.03,51.31 18.03,50.7 17.75,50.42 14.35,50.42 14.1,50.67 14.1,51.43
V3_3DREG on L4_SIG2: 61.47,19.43 65.41,19.43 66.29,18.54 66.29,15.37 67.44,14.22 69.22,14.22 69.98,13.46 69.98,9.65 67.03,6.71 62.92,6.71 60.83,8.79 60.83,18.8
V3_3DREG on L4_SIG2: 55.52,107.42 56.52,108.41 57.1,108.41 57.38,108.13 57.38,106.91 56.41,105.94 55.91,105.94 55.52,106.32
V3_3DREG on L4_SIG2: 13.97,51.43 17.4,51.43 17.93,50.9 17.93,50.06 17.4,49.53 13.97,49.53 13.34,50.16 13.34,50.8
V3_3FTDI on BOTTOM (solid shape): outline of 242 points within 110.88,55.5 119.89,68.58
V3_3FTDI on TOP: 121.92,58.17 123.32,56.77 129.16,56.77 132.21,53.72 132.21,52.45 131.44,51.69 127.89,51.69 124.84,54.74 121.92,54.74 121.54,55.12 121.54,55.88 121.28,56.13 113.28,56.13 111.76,54.61 111.76,51.94 114.17,49.53 114.17,45.34 113.79,44.96 108.08,44.96 107.31,45.72 107.31,54.74 110.74,58.17
V3_3FTDI on TOP: 128.65,67.44 127.76,68.33 127.76,69.09 128.65,69.98 133.48,69.98 137.41,73.91 137.41,74.8 137.8,75.18 138.3,75.18 138.68,74.8 138.68,70.1 136.02,67.44
V3_3FTDI on BOTTOM: 127.76,67.82 129.03,67.82 129.29,67.56 129.29,65.66 130.05,64.9 130.05,64.52 129.79,64.26 128.02,64.26 127.51,64.77 127.51,67.56
V3_3FTDI on BOTTOM: 131.19,50.67 132.08,50.67 132.08,52.83 131.83,53.09 131.44,53.09 131.19,52.83
V3_3FTDI on L3_SIG1: 119.45,56.01 112.08,56.01 112.08,65.73 112.9,66.55 112.9,69.09 113.28,69.47 129.79,69.47 130.94,68.33 130.94,65.41 129.54,64.01 123.51,64.01 120.62,61.12 119.45,59.95
V3_3MTR on L3_SIG1: 52.45,23.37 59.05,23.37 60.2,22.23 60.2,21.08 60.83,20.45 61.47,20.45 62.86,21.84 62.86,33.78 58.93,37.72 51.56,37.72 48.26,41.02 41.27,41.02 40.13,39.88 40.13,36.2 40.89,35.43 49.02,35.43 49.91,34.54 58.67,34.54 60.07,33.15 60.07,28.58 57.53,26.03 52.58,26.03 51.69,25.15 51.69,24.13
V5_0D on BOTTOM (solid shape): outline of 122 points within 8.89,52.2 20.57,57.28
V5_0D on TOP: 125.98,117.98 125.98,116.71 126.11,116.59 127.76,116.59 127.89,116.71 127.89,117.98 127.64,118.24 126.24,118.24
V5_0D on BOTTOM: 30.61,20.83 31.62,20.83 31.75,20.95 31.75,23.11 31.24,23.11 30.48,22.35 30.48,20.95
V5_0D on BOTTOM: 110.74,112.39 103.76,105.41 98.42,105.41 97.92,105.92 90.3,105.92 88.65,107.57 88.65,116.33 90.42,118.11 125.98,118.11 126.11,118.24 128.02,118.24 128.27,117.98 128.27,117.35 127.76,116.84 127,116.84 126.75,116.59 126.75,115.32 126.49,115.06 123.32,115.06 120.65,112.39
V5_0D on L4_SIG2: 1.91,11.43 1.91,107.95 12.07,118.11 103.38,118.11 104.27,117.22 104.27,111.38 101.98,109.09 46.99,109.09 44.4,106.5 27.46,106.5 25.53,108.43 16.87,108.43 11.94,103.5 11.94,19.3 14.86,16.38 20.83,16.38 28.7,24.26 32.89,24.26 38.1,19.05 38.1,15.75 36.32,13.97 36.32,8.76 32.77,5.21 8.13,5.21
V5_0VOP on L4_SIG2: 76.81,105.26 80.06,105.26 80.7,104.62 80.7,96.7 76.96,92.96 73.41,92.96 72.64,93.73 72.64,95.38 73.28,96.01 73.66,96.01 76.45,98.81 76.45,104.9
V24_0D on TOP (solid shape): 121.03,41.66 121.03,40 121.67,39.37 123.44,39.37 124.08,38.73 124.08,36.7 123.44,36.07 119.76,36.07 119.13,36.7 119.13,37.18 119.13,39.91 118.78,40.26 116.46,40.26 116.33,40.39 116.33,41.27 116.59,41.53 119.38,41.53 119.63,41.78 120.9,41.78
V24_0D on TOP: 34.42,53.98 34.04,54.36 32.26,54.36 31.75,54.86 31.75,55.37 30.61,56.52 27.18,56.52 25.53,54.86 21.72,54.86 21.34,55.24 21.34,58.55 21.59,58.8 22.48,58.8 22.73,58.55 22.73,56.52 22.99,56.26 24.51,56.26 26.8,58.55 33.02,58.55 33.78,59.31 35.94,59.31 36.45,58.8 36.45,54.1 36.83,53.72 38.99,53.72 39.24,53.47 39.24,52.58 38.99,52.32 36.32,52.32 36.2,52.2 34.54,52.2 34.42,52.32
V24_0D on TOP: 55.24,109.6 55.5,109.35 55.5,108.58 55.24,108.33 52.58,108.33 52.32,108.08 50.93,108.08 50.8,108.2 50.8,109.86 49.53,111.12 49.53,114.81 49.91,115.19 52.32,115.19 52.7,114.81 52.7,110.11 53.21,109.6
V24_0D on TOP: 118.87,77.47 118.62,77.72 118.62,78.61 118.87,78.87 121.54,78.87 121.79,79.12 123.19,79.12 123.32,78.99 123.32,77.34 123.95,76.71 125.73,76.71 126.36,76.07 126.36,74.04 125.73,73.41 122.05,73.41 121.41,74.04 121.41,77.09 121.03,77.47
V24_0D on TOP: 112.52,17.91 120.52,17.91 121.79,19.18 121.79,26.29 121.28,26.8 119.51,26.8 119.25,26.54 117.35,26.54 116.97,26.16 112.27,26.16 111.63,25.53 111.63,18.8
V24_0D on BOTTOM: 112.27,17.91 120.52,17.91 121.79,19.18 121.79,26.8 120.14,28.45 113.54,28.45 111.76,26.67 111.76,18.41
V24_0D on L5_PWR: 50.67,118.62 136,118.62 138.09,116.53 138.09,2.84 136.53,1.27 55.37,1.27 54.48,2.16 41.53,2.16 41.27,1.91 3.17,1.91 1.91,3.17 1.91,46.99 2.79,47.88 24.89,47.88 26.54,49.53 26.54,52.32 33.66,59.44 35.69,59.44 36.83,58.29 36.83,42.67 30.86,36.7 30.86,31.37 27.76,28.27 27.76,18.34 33.27,12.83 108.71,12.83 111.89,16 111.89,32.77 120.14,41.02 120.14,60.58 124.84,65.28 124.84,68.33 120.14,73.02 120.14,104.77 118.11,106.81 91.41,106.81 89.79,108.43 84.68,108.43 83.06,106.81 50.55,106.81 48.89,108.46 48.89,116.84
V24_0MTR on TOP: 14.73,23.75 20.7,23.75 21.34,23.11 21.34,16.89 20.57,16.13 17.14,16.13 14.1,19.18 14.1,23.11
V24_0MTR on BOTTOM: 16.26,16.51 21.46,16.51 22.23,17.27 22.23,22.35 21.72,22.86 16.51,22.86 15.75,22.1 15.75,21.08 15.11,20.45 15.11,17.65
V24_0MTR on BOTTOM: 36.32,36.2 39.75,36.2 40,35.94 40,33.78 39.88,33.66 37.72,33.66 37.21,33.15 37.21,29.84 36.96,29.59 35.56,29.59 35.18,29.97 35.18,35.05
V24_0MTR on L4_SIG2: 46.1,29.46 46.1,26.67 44.7,25.27 28.32,25.27 20.07,17.02 17.14,17.02 16.26,17.91 16.26,23.75 24.38,31.88 43.69,31.88
VDD_CORE on BOTTOM (solid shape): 110.24,50.55 110.24,45.21 109.6,44.58 109.25,44.58 109.22,44.59 109.17,44.61 109.1,44.62 109.04,44.63 108.98,44.62 108.92,44.61 108.86,44.59 108.83,44.58 104.52,44.58 103.63,45.47 103.63,47.53 107.62,47.53 107.62,47.47 107.63,47.41 107.64,47.35 107.67,47.3 107.7,47.24 107.73,47.2 107.77,47.15 107.82,47.12 107.87,47.09 107.93,47.06 107.99,47.05 108.05,47.04 108.11,47.04 108.17,47.05 108.22,47.06 108.28,47.09 108.33,47.12 108.38,47.15 108.42,47.2 108.46,47.24 108.49,47.3 108.51,47.35 108.53,47.41 108.53,47.47 108.53,47.53 108.53,47.59 108.51,47.65 108.49,47.7 108.46,47.75 108.42,47.8 108.38,47.84 108.33,47.88 108.28,47.91 108.22,47.93 108.17,47.95 108.11,47.96 108.05,47.96 107.99,47.95 107.93,47.93 107.87,47.91 107.82,47.88 107.77,47.84 107.73,47.8 107.7,47.75 107.67,47.7 107.64,47.65 107.63,47.59 107.62,47.53 103.63,47.53 103.63,47.62 103.12,48.13 98.42,48.13 97.92,48.64 97.92,50.42 98.68,51.18 109.6,51.18
VDD_CORE on TOP: 56.77,15.88 58.55,15.88 58.93,15.49 58.93,14.35 58.17,13.59 57.28,13.59 56.39,14.48 56.39,15.49
VDD_CORE on BOTTOM: 106.05,65.91 107.57,65.91 108.08,65.41 108.08,64.14 107.57,63.63 105.92,63.63 105.41,64.14 105.41,65.28
VDD_CORE on L3_SIG1: 79.5,67.95 82.17,67.95 83.06,67.06 83.06,65.41 82.3,64.64 78.49,64.64 77.85,65.28 77.85,66.29
VDD_CORE on L5_PWR: 107.95,44.7 102.62,44.7 96.65,50.67 96.65,53.24 95.71,54.18 95.3,54.18 94.41,55.07 94.41,55.83 86.11,64.14 78.99,64.14 77.98,65.15 77.98,66.04 79.12,67.18 79.12,67.69 80.64,69.22 80.64,70.99 81.28,71.63 94.36,71.63 95.5,70.48 95.5,67.18 104.77,57.91 104.77,52.7 106.81,50.67 108.46,50.67 109.98,49.15 109.98,46.74
VDD_COREREG on BOTTOM (solid shape): 118.36,48.64 118.36,42.55 118.11,42.29 112.14,42.29 111.38,41.53 109.98,41.53 109.73,41.78 109.73,42.16 112.14,44.58 112.65,44.58 114.05,45.97 114.05,46.86 114.17,46.99 116.46,46.99 116.84,47.37 116.84,48.64 117.09,48.89 118.11,48.89
VDD_MPU on TOP: 90.8,90.42 96.27,90.42 97.92,88.77 97.92,85.6 97.28,84.96 93.73,84.96 93.22,85.47 93.22,87.12 92.84,87.5 90.93,87.5 90.55,87.88 90.55,90.17
VDD_MPU on TOP: 87.38,84.33 89.03,84.33 89.15,84.2 89.15,82.55 88.77,82.17 87.5,82.17 87.12,82.55 87.12,84.07
VDD_MPU on TOP: 64.45,27.49 65.23,27.49 65.66,27.06 65.66,25.93 65.13,25.4 64.39,25.4 64.01,25.78 64.01,27.05
VDD_MPU on BOTTOM: 94.36,87.88 96.65,87.88 96.9,88.14 97.41,88.14 97.79,87.76 97.79,85.47 97.41,85.09 93.6,85.09 93.22,85.47 93.22,87.76 93.6,88.14 94.11,88.14
VDD_MPU on L3_SIG1: 64.68,27.53 65.82,27.53 66.67,26.67 66.67,25.65 66.04,25.02 65.02,25.02 64.38,25.66 64.38,27.23
VDD_MPU on L3_SIG1: 78.11,69.34 78.99,69.34 79.38,68.96 79.38,68.33 78.74,67.69 77.85,67.69 77.6,67.95 77.6,68.83
VDD_MPU on L5_PWR: 97.79,89.53 97.79,82.42 95.38,80.01 95.38,73.41 94.36,72.39 81.41,72.39 80.01,70.99 80.01,69.85 78.74,68.58 78.74,67.44 78.36,67.06 77.95,67.06 77.57,67.44 77.57,68.48 76.2,69.85 76.2,74.3 93.09,91.19 96.14,91.19
VDD_MPU_OUT on BOTTOM: 98.93,95.5 94.49,95.5 93.85,94.87 93.85,93.47 94.36,92.96 100.46,92.96 100.84,93.34 100.84,93.6
VDD_MPU_SENSE on BOTTOM: 94.11,92.58 97.79,92.58 98.04,92.33 98.04,88.52 97.79,88.27 94.74,88.27 93.85,89.15 93.85,92.33
VDDA_MC_ADC on BOTTOM: 101.22,72.26 103,72.26 103.25,72.01 103.25,70.36 103.12,70.23 102.49,70.23 101.98,69.72 101.35,69.72 100.97,70.1 100.97,72.01
VDDR_VREF on TOP: 83.31,11.94 78.93,16.32 78.93,17.97 75.31,21.59 75.31,23.11 76.07,23.88 78.74,23.88 87.63,14.99 90.42,14.99 92.2,13.21 92.96,13.21 93.09,13.08 93.09,12.07 92.96,11.94
VDDR_VREF on BOTTOM: 84.84,33.15 87.38,33.15 87.63,32.89 87.63,31.75 86.11,30.23 84.2,30.23 83.31,31.12 83.31,31.62
VDDR_VREF on BOTTOM: 67.77,35.05 68.96,35.05 69.34,34.67 69.34,34.16 70.66,32.84 70.66,28.19 69.65,27.18 68.48,27.18 67.06,28.6 67.06,29.54 66.55,30.05 66.55,33.83
VDDR_VREF on BOTTOM: 73.79,27.69 77.34,27.69 78.61,26.42 78.61,23.24 77.85,22.48 76.33,22.48 73.41,25.4 73.41,27.3
VDDR_VREF on L4_SIG2: 94.08,32.26 96.27,32.26 97.1,31.42 97.1,27.03 96.39,26.31 94.23,26.31 93.42,27.13 93.42,31.6
VDDR_VTT on TOP: 92.21,18.13 92.21,20.26 91.5,20.97 84.31,20.97 84.07,21.21 84.07,21.97 84.33,22.23 88.39,22.23 89.92,23.75 96.52,23.75 101.85,29.08 101.85,32.38 102.11,32.64 103.5,32.64 103.89,32.26 103.89,26.02 99.59,21.72 96.39,21.72 96.14,21.97 94.23,21.97 93.77,21.51 93.77,17.85 92.71,17.85 92.42,18.13
VDDR_VTT on BOTTOM: 97.16,20.83 96.01,21.97 94.36,21.97 92.33,19.94 88.9,19.94 86.86,17.9 84.57,17.9 83.82,18.65 83.82,24.18 83.11,24.89 83.11,28.5 83.95,29.34 84.45,29.34 84.84,28.96 84.84,26.42 86.11,25.15 98.68,25.15 100.58,27.05 100.58,30.23 103.25,32.89 103.25,33.4 101.6,35.05 99.19,35.05 98.81,35.43 98.81,35.94 99.19,36.32 103.76,36.32 104.39,35.69 104.39,27.67 103.77,27.05 103.77,21.73 102.87,20.83
VDDS_DDR on TOP: 87.12,27.94 87.76,27.3 90.42,27.3 95.12,32 95.12,33.91 94.61,34.42 94.61,36.07 94.23,36.45 88.77,36.45 87.12,34.8
VDDS_DDR on TOP: 94.74,16.51 95.12,16.89 95.12,17.4 95.76,18.03 95.76,19.56 96.14,19.94 96.14,21.39 95.94,21.59 94.49,21.59 94.23,21.34 94.23,16.51
VDDS_DDR on BOTTOM: 79.88,16 76.07,19.81 71.96,19.81 63.5,28.27 63.5,36.58 63.25,36.83 63.25,42.19 63.63,42.57 64.82,42.57 65.68,41.71 65.68,39.52 66.22,38.99 66.22,29.92 66.67,29.47 66.67,28.45 68.83,26.29 69.6,26.29 70.74,25.15 73.02,25.15 76.07,22.1 78.11,22.1 79.04,23.04 81.13,23.04 82.37,24.28 83.03,24.28 83.44,23.88 83.44,16.51 84.07,15.88 86.74,15.88 90.3,19.43 92.33,19.43 94.49,21.59 95.76,21.59 96.01,21.34 96.01,18.16 95.89,18.03 93.85,18.03 91.19,15.37 88.14,15.37 87.12,14.35 83.95,14.35 82.3,16
VDDS_DDR on L3_SIG1: 78.61,30.73 77.6,30.73 75.06,33.27 75.06,33.78 75.56,34.29 77.72,34.29 78.87,33.15 78.87,30.99
VDDS_DDR on L3_SIG1: 87.88,37.97 87.12,38.73 71.88,38.73 70.48,37.34 70.48,35.69 71.25,34.92 71.25,29.46 70.1,28.32 64.39,28.32 64.01,28.7 64.01,34.54 63.37,35.18 63.37,43.56 64.77,44.96 65.53,44.96 66.42,44.07 66.42,41.91 66.67,41.66 97.66,41.66 97.66,28.7 97.03,28.07 95.89,28.07 95.76,28.19 95.76,32 95.38,32.38 94.23,32.38 92.33,34.29 90.04,34.29 87.88,36.45
VDDS_DDR on L4_SIG2: 69.72,34.42 77.85,34.42 79.38,35.94 79.38,40.26 78.11,41.53 69.6,41.53 69.22,41.15 69.22,34.92
VDDS_DDR on L4_SIG2: 94.11,21.59 94.11,18.67 94.61,18.16 94.61,15.88 96.39,14.1 98.81,14.1 99.06,14.35 99.06,16 98.42,16.64 98.42,17.27 97.28,18.41 97.28,21.34 96.65,21.97 94.49,21.97
(no net) on TOP: 53.21,109.98 55.37,109.98 56.59,111.2 56.59,113.84 56.39,114.05 54.61,114.05 53.09,112.52 53.09,110.11
(no net) on TOP: 43.31,27.18 43.56,27.43 43.69,27.43 44.32,26.8 45.34,26.8 46.61,25.53 46.61,22.35 47.24,21.72 50.93,21.72 51.56,21.08 51.56,17.4 50.8,16.64 47.6,16.64 47.43,16.81 47.43,16.81 43.69,20.55 43.69,26.42 43.31,26.8
(no net) on TOP: 54.99,56.26 54.99,54.1 54.36,53.47 52.96,53.47 52.45,53.98 52.45,56.26 52.7,56.52 54.74,56.52
(no net) on TOP: 42.04,24.89 42.04,27.05 42.29,27.3 42.8,27.3 42.8,27.05 42.93,26.92 42.93,17.14 42.55,16.76 38.23,16.76 37.85,17.14 37.85,20.7
(no net) on TOP: 116.59,40.13 116.33,40.39 116.33,41.27 116.59,41.53 119.38,41.53 119.63,41.78 120.9,41.78 121.03,41.66 121.03,40 121.67,39.37 123.44,39.37 124.08,38.73 124.08,36.7 123.44,36.07 119.76,36.07 119.13,36.7 119.13,39.75 118.75,40.13
(no net) on TOP: 52.2,71.75 52.2,70.23 51.56,69.6 49.66,69.6 49.15,70.1 49.15,72.14 49.53,72.52 51.43,72.52
(no net) on TOP: 58.04,109.98 60.07,109.98 60.32,110.24 60.32,114.81 59.94,115.19 57.4,115.19 56.9,114.68 56.9,111.12
(no net) on TOP: 52.2,65.79 52.2,64.01 51.43,63.25 49.66,63.25 49.15,63.75 49.15,65.15 50.04,66.04 51.94,66.04
(no net) on TOP: 38.61,25.4 40.64,27.43 40.64,29.72 40.89,29.72 40.89,28.07 41.32,27.65 41.32,25.82 36.45,20.95 36.45,19.05 34.16,16.76 30.48,16.76 29.84,17.4 29.84,19.56 35.69,25.4
(no net) on TOP: 120.9,77.22 118.62,77.22 117.53,76.12 117.53,73.36 117.73,73.15 119.51,73.15 121.03,74.68 121.03,77.09
(no net) on TOP: 63.25,111.63 62.99,111.38 61.47,111.38 61.21,111.63 61.21,115.82 61.47,116.08 62.99,116.08 63.25,115.82
(no net) on TOP: 122.17,42.67 126.87,42.67 127.76,41.78 127.76,40.13 127.38,39.75 121.92,39.75 121.54,40.13 121.54,42.04
(no net) on TOP: 36.96,53.98 39.24,53.98 40.34,55.07 40.34,57.84 40.13,58.04 38.35,58.04 36.83,56.52 36.83,54.1
(no net) on TOP: 41.78,53.98 43.81,53.98 44.07,54.23 44.07,58.55 43.56,59.05 41.15,59.05 40.64,58.55 40.64,55.12
(no net) on TOP: 22.99,53.98 22.99,51.94 23.24,51.69 29.21,51.69 29.59,52.07 29.59,53.59 29.21,53.98 24.77,53.98 24.51,54.23 23.24,54.23
(no net) on TOP: 127.95,110.04 127.95,106.23 127.25,105.54 125.09,105.54 125.09,107.19 125.92,108.01 125.92,109.79 126.3,110.17 127.82,110.17
(no net) on TOP: 52.32,78.61 52.32,76.33 51.94,75.95 49.78,75.95 49.28,76.45 49.28,78.74 49.78,79.25 51.69,79.25
(no net) on TOP: 118.62,39.88 116.33,39.88 115.24,38.79 115.24,36.02 115.44,35.81 117.22,35.81 118.75,37.34 118.75,39.75
(no net) on TOP: 116.08,77.22 114.05,77.22 113.79,76.96 113.79,72.64 114.17,72.26 116.84,72.26 117.22,72.64 117.22,76.07
(no net) on TOP: 110.87,75.56 111.12,75.82 112.65,75.82 112.9,75.56 112.9,72.52 112.65,72.26 111.12,72.26 110.87,72.52
(no net) on TOP: 52.2,56.26 52.2,54.48 51.43,53.72 49.66,53.72 49.15,54.23 49.15,56.26 49.4,56.52 51.94,56.52
(no net) on TOP: 54.99,71.75 54.99,69.72 54.61,69.34 52.83,69.34 52.45,69.72 52.45,71.75 52.7,72.01 54.74,72.01
(no net) on TOP: 55.12,77.85 55.12,76.33 54.74,75.95 52.96,75.95 52.58,76.33 52.58,78.61 52.83,78.87 54.1,78.87
(no net) on TOP: 22.99,58.67 22.99,56.64 23.11,56.52 24.26,56.52 24.51,56.77 24.51,58.55 24.26,58.8 23.11,58.8
(no net) on TOP: 46.46,29.87 37.46,29.87 37.46,28.58 36.58,28.58 36.58,34.04 36.83,34.29 37.34,34.29 37.59,34.04 37.59,33.53 47.37,33.53 47.37,34.67 48.26,34.67 48.39,34.54 48.39,28.19 48.26,28.07 46.51,28.07 46.46,28.12
(no net) on TOP: 46.99,55.63 46.74,55.37 45.21,55.37 44.96,55.63 44.96,58.67 45.21,58.93 46.74,58.93 46.99,58.67
(no net) on TOP: 28.07,50.67 30.23,50.67 30.48,50.42 30.48,48.89 30.23,48.64 28.07,48.64 27.81,48.89 27.81,50.42
(no net) on TOP: 54.61,63.25 52.83,63.25 52.45,63.63 52.45,66.04 52.96,66.55 54.99,66.55 55.24,66.29 55.24,63.88
(no net) on TOP: 113.79,39.88 111.76,39.88 111.51,39.62 111.51,35.31 112.01,34.8 114.43,34.8 114.94,35.31 114.94,38.73
(no net) on TOP: 108.58,38.23 108.84,38.48 110.36,38.48 110.62,38.23 110.62,35.18 110.36,34.92 108.84,34.92 108.58,35.18
(no net) on TOP: 130.62,110.8 130.62,112.2 130.24,112.58 126.55,112.58 123.76,109.79 123.76,106.13 124.34,105.55 124.5,105.55 124.77,105.83 124.77,107.63 125.54,108.39 125.54,110.04 126.04,110.55 130.36,110.55
(no net) on BOTTOM: 116.72,58.17 116.72,59.57 116.84,59.69 121.29,59.69 121.8,59.18 121.8,58.42 121.67,58.3 120.78,58.3 120.65,58.42 119.51,58.42 119.26,58.17
(no net) on BOTTOM: 112.27,71.25 114.3,71.25 114.68,70.87 114.68,69.22 114.43,68.96 112.14,68.96 111.76,69.34 111.76,70.74
(no net) on BOTTOM: 60.32,111.51 60.32,114.81 59.94,115.19 55.75,115.19 54.61,114.05 54.61,111.63 55.12,111.12 59.94,111.12
(no net) on BOTTOM: 118.11,42.29 112.14,42.29 111.38,41.53 109.98,41.53 109.73,41.78 109.73,42.16 112.14,44.58 112.65,44.58 114.05,45.97 114.05,46.86 114.17,46.99 116.46,46.99 116.84,47.37 116.84,48.64 117.09,48.89 118.11,48.89 118.36,48.64 118.36,42.55
(no net) on BOTTOM: 107.82,104.07 107.57,104.33 105.72,104.33 105.41,104.01 105.41,102.62 105.79,102.23 107.19,102.23 107.7,101.73 108.71,101.73 109.09,102.11 109.09,103.95 108.97,104.07
(no net) on BOTTOM: 112.52,46.1 111,46.1 110.74,46.35 110.74,47.37 111,47.62 112.01,47.62 112.78,46.86 112.78,46.35
(no net) on BOTTOM: 24.26,54.36 24.26,52.07 24.64,51.69 29.21,51.69 29.59,52.07 29.59,54.74 30.61,55.75 30.61,57.02 30.35,57.28 27.18,57.28
(no net) on BOTTOM: 55.12,79.12 55.12,76.58 54.48,75.95 53.34,75.95 52.58,76.71 52.58,80.52 52.83,80.77 53.47,80.77
(no net) on BOTTOM: 55.24,66.29 55.24,63.88 54.61,63.25 52.83,63.25 52.45,63.63 52.45,67.69 52.7,67.95 53.59,67.95
(no net) on BOTTOM: 54.99,56.9 54.99,54.1 54.36,53.47 52.96,53.47 52.45,53.98 52.45,58.29 52.7,58.55 53.34,58.55
(no net) on BOTTOM: 107.31,106.81 105.79,106.81 105.41,106.43 105.41,105.03 105.73,104.71 107.44,104.71 107.7,104.96 107.7,106.43
(no net) on BOTTOM: 138.66,59.56 138.66,55.12 135.73,55.12 135.23,55.63 135.23,60.93 136.75,60.93 136.88,60.8 136.88,59.56
(no net) on BOTTOM: 47.62,29.84 38.1,29.84 37.72,30.23 37.72,33.27 37.97,33.53 41.27,33.53 41.53,33.78 41.53,36.2 41.91,36.58 43.31,36.58 43.69,36.2 43.69,33.78 43.94,33.53 47.62,33.53 47.88,33.27 47.88,30.1
(no net) on BOTTOM: 52.2,70.23 51.56,69.6 49.66,69.6 49.15,70.1 49.15,72.39 50.93,74.17 51.94,74.17 52.2,73.91
(no net) on BOTTOM: 17.02,60.32 14.48,60.32 13.97,59.82 13.97,57.78 14.35,57.4 17.14,57.4 17.4,57.66 17.4,59.94
(no net) on BOTTOM: 37.46,51.56 43.56,51.56 44.32,52.32 45.59,52.32 45.85,52.07 45.85,51.69 43.31,49.15 42.8,49.15 41.53,47.88 41.53,46.86 39.62,44.96 37.46,44.96 37.21,45.21 37.21,51.31
